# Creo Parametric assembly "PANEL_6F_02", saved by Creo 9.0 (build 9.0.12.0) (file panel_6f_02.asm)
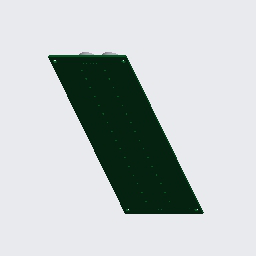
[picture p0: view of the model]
Units: millimeter Newton Second (mmNs); MM, TONNE, SECS

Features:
  1. coordinate system "PANEL_6F_02"
  2. imported feature "Import Feature id 4"
  3. component "PCB_6F"
  4. component "TX_6F_T1"
  5. component "TX_6F_T1"
  6. component "TX_6F_T1"
  7. component "TX_6F_T1"
  8. component "TX_6F_T1"
  9. component "TX_6F_T1"
  10. component "TX_6F_T1"
  11. component "TX_6F_T1"
  12. component "TX_6F_T1"
  13. component "TX_6F_T1"
  14. component "TX_6F_T1"
  15. component "TX_6F_T1"
  16. component "TX_6F_T1"
  17. component "TX_6F_T1"
  18. component "TX_6F_T1"
  19. component "TX_6F_T1"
